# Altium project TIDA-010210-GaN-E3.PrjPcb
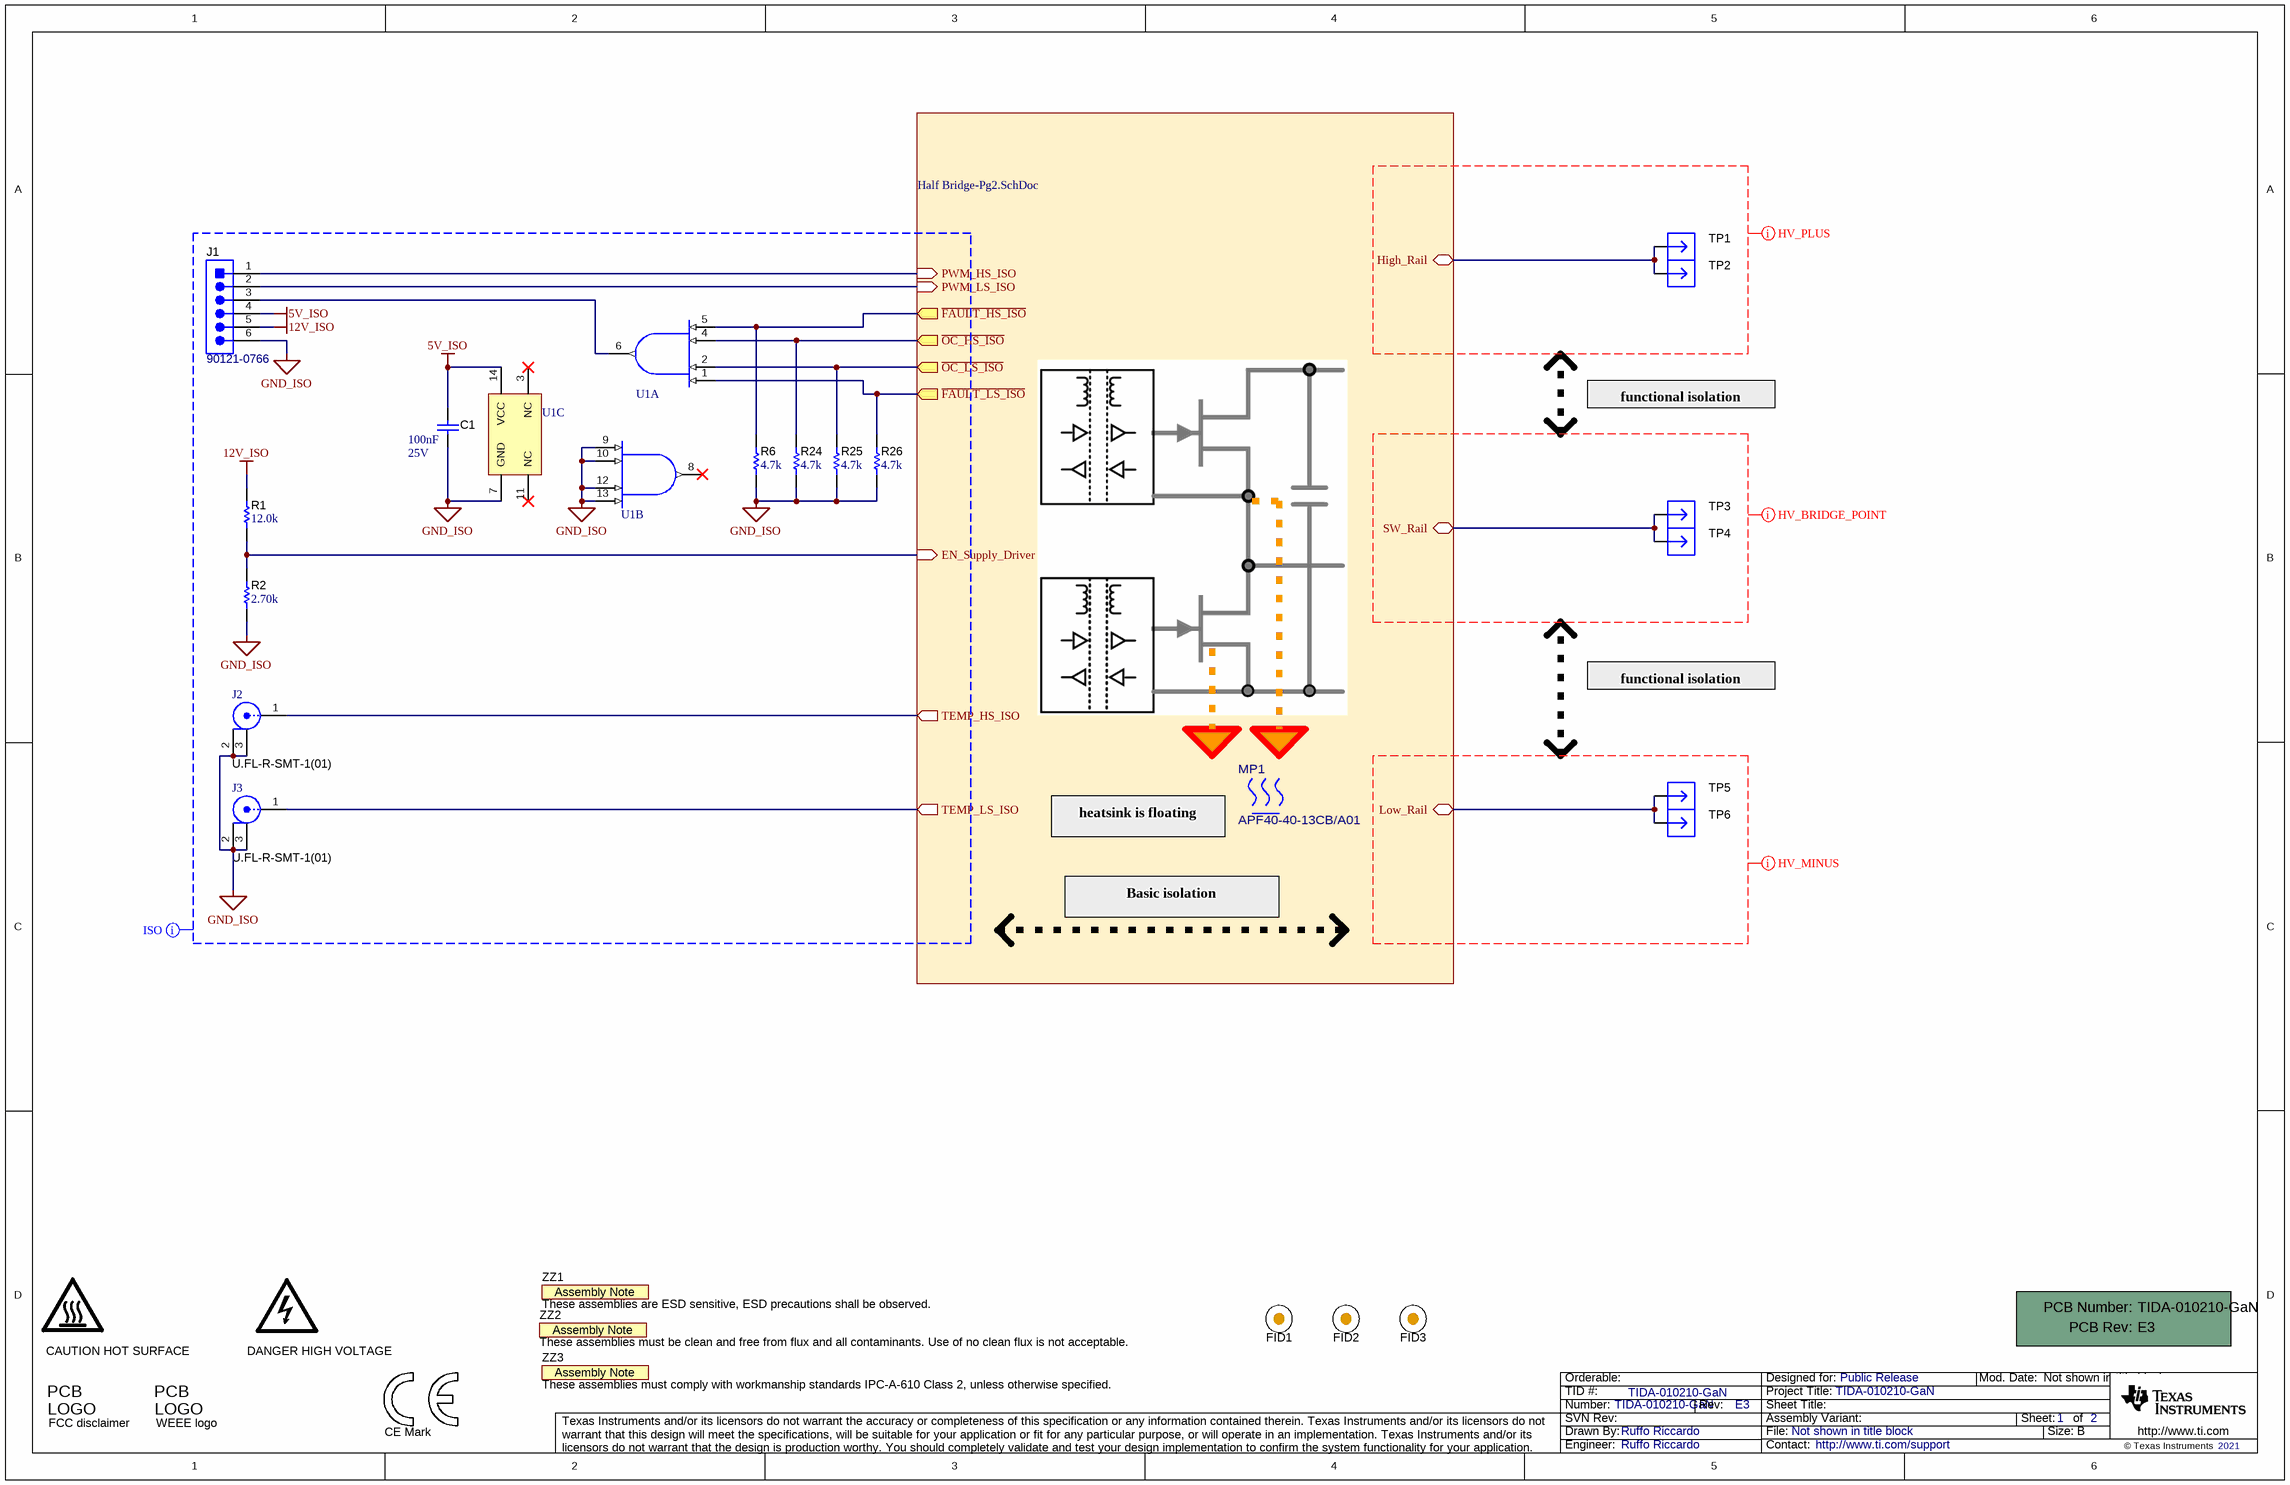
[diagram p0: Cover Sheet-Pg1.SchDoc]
CopyrightYear: 2021; DrawnBy: Ruffo Riccardo; PCB_Layout: Ruffo Riccardo; PCB_Rev: E3; PRJ_Customer: Public Release; PRJ_Engineer: Ruffo Riccardo; PRJ_Number: TIDA-010210-GaN; PRJ_Title: TIDA-010210-GaN; SCH_Rev: E3; TechSupport: http://www.ti.com/support; TID: TIDA-010210-GaN
2 sheets, 108 parts. Net scope: hierarchical (ports join the sheet entries above them; power ports are global).
Board file: TIDA-010210-GaN-E3.PcbDoc
Sheets:
  Cover Sheet-Pg1.SchDoc
    U_Half_Bridge = Half Bridge-Pg2.SchDoc

## Sheet Cover Sheet-Pg1.SchDoc
size 431 x 279 mm; Date: Not shown in title block; ApprovedBy: Not shown in title block; CheckedBy: Not shown in title block; Author: Not shown in title block; CompanyName: Not shown in title block; Engineer: Not shown in title block; Organization: Not shown in title block; Address1: Not shown in title block; Address2: Not shown in title block; Address3: Not shown in title block; Address4: Not shown in title block; DocumentNumber: 1; Revision: Use project parameter SCH_Rev; SheetNumber: 1; SheetTotal: 2; PageSetup: Record=PageOptions¦CenterHorizontal=True¦CenterVertical=True¦PrintScale=1.00¦XCorrection=1.00¦YCorrection=1.00¦PrintKind=0¦BorderSize=5000000¦LeftOffset=0¦BottomOffset=0¦Orientation=2¦PaperLength=1000¦PaperWidth=1000¦Scale=100¦PaperSource=15¦PrintQuality=600¦MediaType=1¦DitherType=10¦PaperKind=Letter¦PrintScaleMode=1

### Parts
!PCB1  Printed Circuit Board  (value not drawn)  (mechanical)
C1  Cap_F: 100nF  VDC_V: 25V  [0603]  (hidden comment: 06033C104JAT2A)
FID1  Fiducial  [Fiducial6.4-20]  (value not drawn)
FID2  Fiducial  [Fiducial6.4-20]  (value not drawn)
FID3  Fiducial  [Fiducial6.4-20]  (value not drawn)
J1  90121-0766  [Molex_90121-0766]
J2  U.FL-R-SMT-1(01)  [CONN_UFL-R-SMT-1]
J3  U.FL-R-SMT-1(01)  [CONN_UFL-R-SMT-1]
LOGO1  CAUTION HOT SURFACE  [IEC_HotSurface_Small]  (no BOM)
LOGO3  DANGER HIGH VOLTAGE  [IEC_HighVoltage_Small]  (no BOM)
Logo5  CE Mark  [CE_Mark_5mm]  (no BOM)
Logo6  FCC disclaimer  [FCC_disclaimer_stacked]  (no BOM)
Logo8  WEEE logo  [WEEE_Minimum]  (no BOM)
MP1  APF40-40-13CB/A01  [FP-APF40-40-13CB-A01_HEATSINK_40MM0_40MM0-MFG]
R1  ValueDisplayed: 12.0k  [0603]  (hidden comment: RC0603FR-0712KL)
R2  ValueDisplayed: 2.70k  [0603]  (hidden comment: RC0603FR-072K7L)
R6  ValueDisplayed: 4.7k  [0603]  (hidden comment: CR0603-JW-472GLF)
R24  ValueDisplayed: 4.7k  [0603]  (hidden comment: CR0603-JW-472GLF)
R25  ValueDisplayed: 4.7k  [0603]  (hidden comment: CR0603-JW-472GLF)
R26  ValueDisplayed: 4.7k  [0603]  (hidden comment: CR0603-JW-472GLF)
TP1  3620-2-32-15-00-00-08-0  [Mill-Max_3620-2-32-xx-00-00-08-0]  (value not drawn)
TP2  3620-2-32-15-00-00-08-0  [Mill-Max_3620-2-32-xx-00-00-08-0]  (value not drawn)
TP3  3620-2-32-15-00-00-08-0  [Mill-Max_3620-2-32-xx-00-00-08-0]  (value not drawn)
TP4  3620-2-32-15-00-00-08-0  [Mill-Max_3620-2-32-xx-00-00-08-0]  (value not drawn)
TP5  3620-2-32-15-00-00-08-0  [Mill-Max_3620-2-32-xx-00-00-08-0]  (value not drawn)
TP6  3620-2-32-15-00-00-08-0  [Mill-Max_3620-2-32-xx-00-00-08-0]  (value not drawn)
U1  SN74AS21D  [D0014A_N]  (value not drawn)  (parts A,B,C of 3)
ZZ1  These assemblies are ESD sensitive, ESD precautions shall be observed.  [AssemblyNote]  (no BOM)
ZZ2  These assemblies must be clean and free from flux and all contaminants. Use of no clean flux is not acceptable.  [AssemblyNote]  (no BOM)
ZZ3  These assemblies must comply with workmanship standards IPC-A-610 Class 2, unless otherwise specified.  [AssemblyNote]  (no BOM)

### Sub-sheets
U_Half_Bridge = Half Bridge-Pg2.SchDoc: TEMP_HS_ISO (out), PWM_HS_ISO (in), TEMP_LS_ISO (out), EN_Supply_Driver (in), PWM_LS_ISO (in), SW_Rail (bidir), High_Rail (bidir), Low_Rail (bidir), ~{OC_LS_ISO} (out), ~{FAULT_LS_ISO} (out), ~{OC_HS_ISO} (out), ~{FAULT_HS_ISO} (out)

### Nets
5V_ISO: C1.1 J1.4 U1.14(VCC)
12V_ISO: J1.5 R1.2
GND_ISO: C1.2 J1.6 J2.2 J2.3 J3.2 J3.3 R2.1 R6.1 R24.1 R25.1 R26.1 U1.7(GND) U1.9(2A) U1.10(2B) U1.12(2C) U1.13(2D)
Low_Rail: TP5.1 TP6.1 ; sheet U_Half_Bridge/Low_Rail
SW_Rail: TP3.1 TP4.1 ; sheet U_Half_Bridge/SW_Rail
EN_Supply_Driver: R1.1 R2.2 ; sheet U_Half_Bridge/EN_Supply_Driver
~{FAULT_HS_ISO}: R6.2 U1.5(1D) ; sheet U_Half_Bridge/~{FAULT_HS_ISO}
~{FAULT_LS_ISO}: R26.2 U1.1(1A) ; sheet U_Half_Bridge/~{FAULT_LS_ISO}
High_Rail: TP1.1 TP2.1 ; sheet U_Half_Bridge/High_Rail
~{OC_HS_ISO}: R24.2 U1.4(1C) ; sheet U_Half_Bridge/~{OC_HS_ISO}
~{OC_LS_ISO}: R25.2 U1.2(1B) ; sheet U_Half_Bridge/~{OC_LS_ISO}
PWM_HS_ISO: J1.1 ; sheet U_Half_Bridge/PWM_HS_ISO
PWM_LS_ISO: J1.2 ; sheet U_Half_Bridge/PWM_LS_ISO
TEMP_HS_ISO: J2.1 ; sheet U_Half_Bridge/TEMP_HS_ISO
TEMP_LS_ISO: J3.1 ; sheet U_Half_Bridge/TEMP_LS_ISO
NetJ1_3: J1.3 U1.6(1Y)

Not connected (* = marked no-connect by the designer): U1 3(NC)* 8(2Y)* 11(NC)*

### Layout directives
net class ISO: 5V_ISO, 12V_ISO, GND_ISO
net class HV_MINUS: (no net found under the mark)
net class HV_BRIDGE_POINT: (no net found under the mark)
net class HV_PLUS: (no net found under the mark)

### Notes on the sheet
- functional isolation
- (near MP1) heatsink is floating
- Basic isolation

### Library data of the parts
!PCB1 = CMP-0003618-2: Manufacturer: Any; PartNumber: TIDA-010210-GaN
C1 = CMP-0006752-5: CAP, CERM, 0.1 uF, 25 V, +/- 5%, X7R, 0603; Manufacturer: AVX; TaMin_C: -55°C; ESR_ohm: 0.05; Polarized: N; SizeAreaWB_mm2: 4.68; Value1: 0.05 ohm; U/M: EA; Value: 0.1uF; TaMax_C: 125°C; SizeZ_mm: 1; SizeX_mm: 1.6; SizeY_mm: 0.8; SizeArea_mm2: 1.28; AEC Category: Q200
FID1-FID3 = CMP-0077181-1: Fiducial mark.  There is nothing to buy or mount.
J1 = CMP-0055334-1: Header, 2.54mm, 6x1, Gold, R/A, TH; Manufacturer: Molex; CNHeader: TRUE; Current_A: 3A; Shrouded: N; Gender: Male; Voltage_V: 350V; Row_Count: 1; Pitch_mm: 2.54; CT: FALSE; Cert_UL: Y
J2 J3 = CMP-0075320-1: Receptacle, Ultra Miniature Coaxial, Male Pin, 50 ohm, SMT; Manufacturer: Hirose Electric Co. Ltd.; CNHeader: False; Gender: Female; ContactFinish: Gold
LOGO1 = CMP-0074837-1: IEC 61010-1 Hot Surface Warning; SymbolCreator: a0412235; Lib Reference: IEC_HotSurface
LOGO3 = CMP-0074835-1: IEC 61010-1 High Voltage Warning; SymbolCreator: a0412235; Lib Reference: IEC_HighVoltage
Logo5 = CMP-0074844-1: SymbolCreator: a0412235
Logo6 = CMP-0074847-1: FCC_disclaimer; Library Reference: Logo
Logo8 = CMP-0074769-1
MP1 = CMP-0093659-2: Heat Sink Assorted (BGA, LGA, CPU, ASIC...) Aluminum - Top Mount; Manufacturer: CTS; Natural Thermal Resistance: 9.9°C/W; Thermal Resistance Forced Air Flow: 2.3°C/W; AEC Qualified: No
R1 = CMP-0022779-5: RES, 12.0 k, 1%, 0.1 W, 0603; Manufacturer: Yageo; Power_W: 100mW; TempCo: 100 ppm/C; Value_Code: 12k0; Value: 12.0k; Res_ohm: 12k; SizeX_mm: 1.6; SizeY_mm: 0.8; SizeZ_mm: 1; Value2: 0.1W; SizeArea_mm2: 1.28; AEC Qualified: N; VDC_V: 75V; AEC Category: Q200; SizeAreaWB_mm2: 4.68
R2 = CMP-0022996-5: RES, 2.70 k, 1%, 0.1 W, 0603; Manufacturer: Yageo; Power_W: 100mW; TempCo: 100 ppm/C; Value_Code: 2k70; Value: 2.70k; Res_ohm: 2.7k; SizeX_mm: 1.6; SizeY_mm: 0.8; SizeZ_mm: 1; Value2: 0.1W; SizeArea_mm2: 1.28; AEC Qualified: N; VDC_V: 75V; AEC Category: Q200; SizeAreaWB_mm2: 4.68
R6 R24-R26 = CMP-0025696-3: RES, 4.7 k, 5%, 0.1 W, 0603; Manufacturer: Bourns; Power_W: 100mW; TempCo: 200 ppm/C; Value_Code: 4k70; U/M: EA; Value: 4.7k; EIA_Code: E24; SizeX_mm: 1.6; SizeY_mm: 0.8; SizeZ_mm: 1; Value2: 0.1W; SizeArea_mm2: 1.28; AEC Qualified: N; VDC_V: 50V; AEC Category: Q200
TP1-TP6 = CMP-0055044-1: PCB Pin, 0.04" DIA, Edge-Mount; Manufacturer: Mill-Max; CompType: PCB Pin; Gender: Male; Row_Count: 1; ContactFinish: Gold; CNHeader: FALSE
U1 = CMP-0054374-1: Dual 4-Input Positive-AND Gates, D0014A, TUBE; Manufacturer: Texas Instruments; F @ Nom Voltage(Max)(Mhz): 125; VCC(Min)(V): 4.5; VCC(Max)(V): 5.5; Voltage(Nom)(V): 5; ICC @ Nom Voltage(Max)(mA): 0.0014; Bits(#): 2; Output Type: TTL; Schmitt Trigger: No; Rating: Catalog; tpd @ Nom Voltage(Max)(ns): 15; Technology Family: AS; Output Drive (IOL/IOH)(Max)(mA): -48/48
ZZ1 = CMP-0077236-1
ZZ2 = CMP-0077237-1
ZZ3 = CMP-0077238-1

## Sheet Half Bridge-Pg2.SchDoc
size 431 x 279 mm; Date: Not shown in title block; ApprovedBy: Not shown in title block; CheckedBy: Not shown in title block; Author: Not shown in title block; CompanyName: Not shown in title block; Engineer: Not shown in title block; Organization: Not shown in title block; Address1: Not shown in title block; Address2: Not shown in title block; Address3: Not shown in title block; Address4: Not shown in title block; DocumentNumber: 2; Revision: Use project parameter SCH_Rev; SheetNumber: 2; SheetTotal: 2; PageSetup: Record=PageOptions¦CenterHorizontal=True¦CenterVertical=True¦PrintScale=1.00¦XCorrection=1.00¦YCorrection=1.00¦PrintKind=0¦BorderSize=5000000¦LeftOffset=0¦BottomOffset=0¦Orientation=2¦PaperLength=1000¦PaperWidth=1000¦Scale=100¦PaperSource=15¦PrintQuality=600¦MediaType=1¦DitherType=10¦PaperKind=Letter¦PrintScaleMode=1
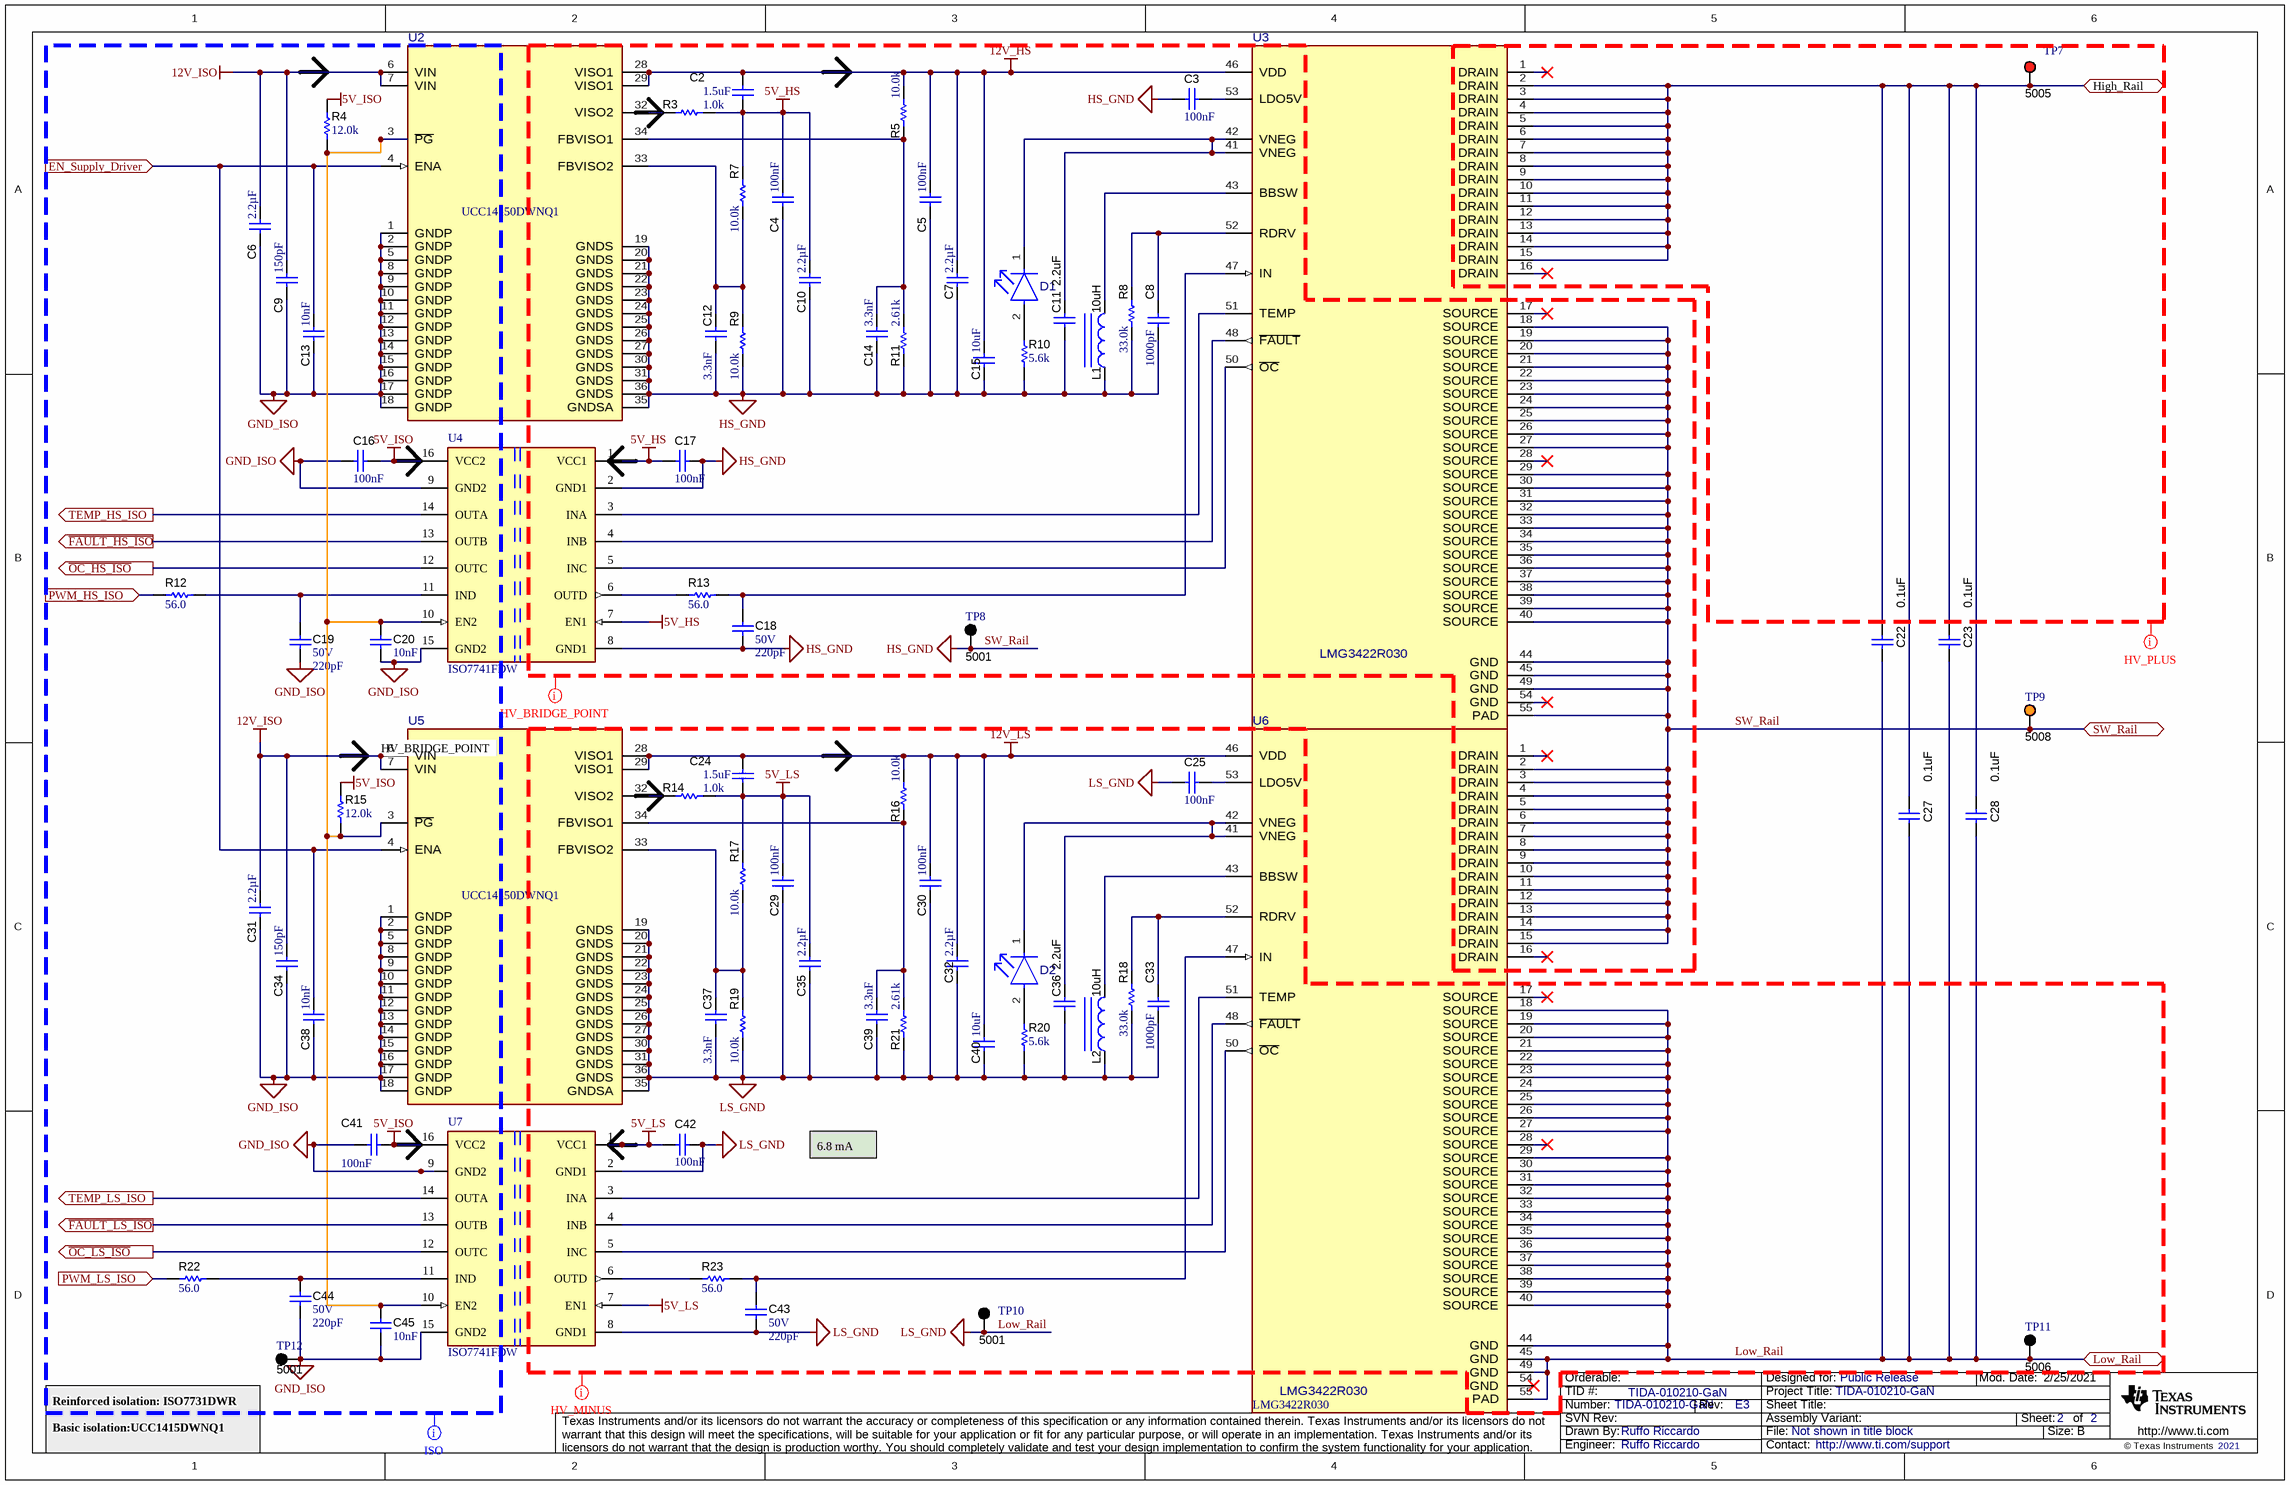
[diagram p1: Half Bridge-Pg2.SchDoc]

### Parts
C2  ValueDisplayed: 1.5uF  [0603]  (hidden comment: C1608X6S1C155K080AC)
C3  Cap_F: 100nF  [0603]  (hidden comment: 06033C104JAT2A)
C4  Cap_F: 100nF  [0603]  (hidden comment: 06033C104JAT2A)
C5  Cap_F: 100nF  [0603]  (hidden comment: 06033C104JAT2A)
C6  ValueDisplayed: 2.2µF  [0603]  (hidden comment: GRM188C71E225KE11D)
C7  ValueDisplayed: 2.2µF  [0603]  (hidden comment: GRM188C71E225KE11D)
C8  ValueDisplayed: 1000pF  [0603]  (hidden comment: C0603C102F3GACTU)
C9  ValueDisplayed: 150pF  [0603]  (hidden comment: GRM1885C1H151JA01D)
C10  ValueDisplayed: 2.2µF  [0603]  (hidden comment: GRM188C71E225KE11D)
C11  ValueDisplayed: 2.2uF  [0805_HV]  (hidden comment: GRM21BR71E225KA73L)
C12  Cap_F: 3.3nF  [0603]  (hidden comment: C0603X332K5RACTU)
C13  Cap_F: 10nF  [0603]  (hidden comment: SR0603X7R103K1NT95(F)#M123A)
C14  Cap_F: 3.3nF  [0603]  (hidden comment: C0603X332K5RACTU)
C15  ValueDisplayed: 10uF  [0805_HV]  (hidden comment: GRM219B31E106MA12)
C16  Cap_F: 100nF  [0603]  (hidden comment: 06033C104JAT2A)
C17  Cap_F: 100nF  [0603]  (hidden comment: 06033C104JAT2A)
C18  VDC_V: 50V  ValueDisplayed: 220pF  [0603]  (hidden comment: C0603C221K5GACTU)
C19  VDC_V: 50V  ValueDisplayed: 220pF  [0603]  (hidden comment: C0603C221K5GACTU)
C20  Cap_F: 10nF  [0603]  (hidden comment: SR0603X7R103K1NT95(F)#M123A)
C22  ValueDisplayed: 0.1uF  [1812_254]  (hidden comment: C1812W104KDRACTU)
C23  ValueDisplayed: 0.1uF  [1812_254]  (hidden comment: C1812W104KDRACTU)
C24  ValueDisplayed: 1.5uF  [0603]  (hidden comment: C1608X6S1C155K080AC)
C25  Cap_F: 100nF  [0603]  (hidden comment: 06033C104JAT2A)
C27  ValueDisplayed: 0.1uF  [1812_254]  (hidden comment: C1812W104KDRACTU)
C28  ValueDisplayed: 0.1uF  [1812_254]  (hidden comment: C1812W104KDRACTU)
C29  Cap_F: 100nF  [0603]  (hidden comment: 06033C104JAT2A)
C30  Cap_F: 100nF  [0603]  (hidden comment: 06033C104JAT2A)
C31  ValueDisplayed: 2.2µF  [0603]  (hidden comment: GRM188C71E225KE11D)
C32  ValueDisplayed: 2.2µF  [0603]  (hidden comment: GRM188C71E225KE11D)
C33  ValueDisplayed: 1000pF  [0603]  (hidden comment: C0603C102F3GACTU)
C34  ValueDisplayed: 150pF  [0603]  (hidden comment: GRM1885C1H151JA01D)
C35  ValueDisplayed: 2.2µF  [0603]  (hidden comment: GRM188C71E225KE11D)
C36  ValueDisplayed: 2.2uF  [0805_HV]  (hidden comment: GRM21BR71E225KA73L)
C37  Cap_F: 3.3nF  [0603]  (hidden comment: C0603X332K5RACTU)
C38  Cap_F: 10nF  [0603]  (hidden comment: SR0603X7R103K1NT95(F)#M123A)
C39  Cap_F: 3.3nF  [0603]  (hidden comment: C0603X332K5RACTU)
C40  ValueDisplayed: 10uF  [0805_HV]  (hidden comment: GRM219B31E106MA12)
C41  Cap_F: 100nF  [0603]  (hidden comment: 06033C104JAT2A)
C42  Cap_F: 100nF  [0603]  (hidden comment: 06033C104JAT2A)
C43  VDC_V: 50V  ValueDisplayed: 220pF  [0603]  (hidden comment: C0603C221K5GACTU)
C44  VDC_V: 50V  ValueDisplayed: 220pF  [0603]  (hidden comment: C0603C221K5GACTU)
C45  Cap_F: 10nF  [0603]  (hidden comment: SR0603X7R103K1NT95(F)#M123A)
D1  KG DELLS1.22-JGKH-24  [FP-KG DELLS1.22-JGKH-24_0603-MFG]  (value not drawn)
D2  KG DELLS1.22-JGKH-24  [FP-KG DELLS1.22-JGKH-24_0603-MFG]  (value not drawn)
L1  ValueDisplayed: 10uH  [WE-LQS_2010]  (hidden comment: 74404020100)
L2  ValueDisplayed: 10uH  [WE-LQS_2010]  (hidden comment: 74404020100)
R3  ValueDisplayed: 1.0k  [0603]  (hidden comment: RC0603JR-071KL)
R4  ValueDisplayed: 12.0k  [0603]  (hidden comment: RC0603FR-0712KL)
R5  ValueDisplayed: 10.0k  [0603]  (hidden comment: M55342K12B10E0T)
R7  ValueDisplayed: 10.0k  [0603]  (hidden comment: M55342K12B10E0T)
R8  ValueDisplayed: 33.0k  [0603]  (hidden comment: RC0603FR-0733KL)
R9  ValueDisplayed: 10.0k  [0603]  (hidden comment: M55342K12B10E0T)
R10  ValueDisplayed: 5.6k  [0603]  (hidden comment: RC0603JR-075K6L)
R11  ValueDisplayed: 2.61k  [0603]  (hidden comment: RC0603FR-072K61L)
R12  ValueDisplayed: 56.0  [0603]  (hidden comment: RC0603FR-0756RL)
R13  ValueDisplayed: 56.0  [0603]  (hidden comment: RC0603FR-0756RL)
R14  ValueDisplayed: 1.0k  [0603]  (hidden comment: RC0603JR-071KL)
R15  ValueDisplayed: 12.0k  [0603]  (hidden comment: RC0603FR-0712KL)
R16  ValueDisplayed: 10.0k  [0603]  (hidden comment: M55342K12B10E0T)
R17  ValueDisplayed: 10.0k  [0603]  (hidden comment: M55342K12B10E0T)
R18  ValueDisplayed: 33.0k  [0603]  (hidden comment: RC0603FR-0733KL)
R19  ValueDisplayed: 10.0k  [0603]  (hidden comment: M55342K12B10E0T)
R20  ValueDisplayed: 5.6k  [0603]  (hidden comment: RC0603JR-075K6L)
R21  ValueDisplayed: 2.61k  [0603]  (hidden comment: RC0603FR-072K61L)
R22  ValueDisplayed: 56.0  [0603]  (hidden comment: RC0603FR-0756RL)
R23  ValueDisplayed: 56.0  [0603]  (hidden comment: RC0603FR-0756RL)
TP7  5005  [Keystone5005]
TP8  5001  [Keystone5001]
TP9  5008  [Keystone5008]
TP10  5001  [Keystone5001]
TP11  5006  [Keystone5006]
TP12  5001  [Keystone5001]
U2  UCC14150DWNQ1  [DWN0036A-MFG]
U3  LMG3422R030  [RQZ0054A-MFG-NV]
U4  ISO7741FDW  [FP-DW0016A-IPC_A]
U5  UCC14150DWNQ1  [DWN0036A-MFG]
U6  LMG3422R030  [RQZ0054A-MFG-NV]
U7  ISO7741FDW  [FP-DW0016A-IPC_A]

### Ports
EN_Supply_Driver (in), High_Rail (bidir), Low_Rail (bidir), PWM_HS_ISO (in), PWM_LS_ISO (in), SW_Rail (bidir), TEMP_HS_ISO (out), TEMP_LS_ISO (out), ~{FAULT_HS_ISO} (out), ~{FAULT_LS_ISO} (out), ~{OC_HS_ISO} (out), ~{OC_LS_ISO} (out)

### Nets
5V_HS: C2.2 C4.1 C10.1 C17.1 R3.2 R7.2 U4.1(VCC1) U4.7(EN1)
5V_ISO: C16.1 C41.1 R4.1 R15.2 U4.16(VCC2) U7.16(VCC2)
5V_LS: C24.2 C29.1 C35.1 C42.1 R14.2 R17.2 U7.1(VCC1) U7.7(EN1)
12V_HS: C2.1 C5.1 C7.1 C15.1 R5.1 U2.28(VISO1) U2.29(VISO1) U3.46(VDD)
12V_ISO: C6.1 C9.1 C31.1 C34.1 U2.6(VIN) U2.7(VIN) U5.6(VIN) U5.7(VIN)
12V_LS: C24.1 C30.1 C32.1 C40.1 R16.1 U5.28(VISO1) U5.29(VISO1) U6.46(VDD)
GND_ISO: C6.2 C9.2 C13.2 C16.2 C19.2 C20.2 C31.2 C34.2 C38.2 C41.2 C44.2 C45.2 TP12.1 U2.1(GNDP) U2.2(GNDP) U2.5(GNDP) U2.8(GNDP) U2.9(GNDP) U2.10(GNDP) U2.11(GNDP) U2.12(GNDP) U2.13(GNDP) U2.14(GNDP) U2.15(GNDP) U2.16(GNDP) U2.17(GNDP) U2.18(GNDP) U4.9(GND2) U4.15(GND2) U5.1(GNDP) U5.2(GNDP) U5.5(GNDP) U5.8(GNDP) U5.9(GNDP) U5.10(GNDP) U5.11(GNDP) U5.12(GNDP) U5.13(GNDP) U5.14(GNDP) U5.15(GNDP) U5.16(GNDP) U5.17(GNDP) U5.18(GNDP) U7.9(GND2) U7.15(GND2)
Low_Rail: C22.2 C23.2 C25.1 C27.2 C28.2 C29.2 C30.2 C32.2 C33.1 C35.2 C36.1 C37.2 C39.2 C40.2 C42.2 C43.2 L2.1 R18.2 R19.1 R20.1 R21.1 TP10.1 TP11.1 U5.19(GNDS) U5.20(GNDS) U5.21(GNDS) U5.22(GNDS) U5.23(GNDS) U5.24(GNDS) U5.25(GNDS) U5.26(GNDS) U5.27(GNDS) U5.30(GNDS) U5.31(GNDS) U5.35(GNDSA) U5.36(GNDS) U6.18(SOURCE) U6.19(SOURCE) U6.20(SOURCE) U6.21(SOURCE) U6.22(SOURCE) U6.23(SOURCE) U6.24(SOURCE) U6.25(SOURCE) U6.26(SOURCE) U6.27(SOURCE) U6.29(SOURCE) U6.30(SOURCE) U6.31(SOURCE) U6.32(SOURCE) U6.33(SOURCE) U6.34(SOURCE) U6.35(SOURCE) U6.36(SOURCE) U6.37(SOURCE) U6.38(SOURCE) U6.39(SOURCE) U6.40(SOURCE) U6.44(GND) U6.45(GND) U6.49(GND) U6.55(PAD) U7.2(GND1) U7.8(GND1) ; port Low_Rail  [also labelled LS_GND]
SW_Rail: C3.1 C4.2 C5.2 C7.2 C8.1 C10.2 C11.1 C12.2 C14.2 C15.2 C17.2 C18.2 L1.1 R8.2 R9.1 R10.1 R11.1 TP8.1 TP9.1 U2.19(GNDS) U2.20(GNDS) U2.21(GNDS) U2.22(GNDS) U2.23(GNDS) U2.24(GNDS) U2.25(GNDS) U2.26(GNDS) U2.27(GNDS) U2.30(GNDS) U2.31(GNDS) U2.35(GNDSA) U2.36(GNDS) U3.18(SOURCE) U3.19(SOURCE) U3.20(SOURCE) U3.21(SOURCE) U3.22(SOURCE) U3.23(SOURCE) U3.24(SOURCE) U3.25(SOURCE) U3.26(SOURCE) U3.27(SOURCE) U3.29(SOURCE) U3.30(SOURCE) U3.31(SOURCE) U3.32(SOURCE) U3.33(SOURCE) U3.34(SOURCE) U3.35(SOURCE) U3.36(SOURCE) U3.37(SOURCE) U3.38(SOURCE) U3.39(SOURCE) U3.40(SOURCE) U3.44(GND) U3.45(GND) U3.49(GND) U3.55(PAD) U4.2(GND1) U4.8(GND1) U6.2(DRAIN) U6.3(DRAIN) U6.4(DRAIN) U6.5(DRAIN) U6.6(DRAIN) U6.7(DRAIN) U6.8(DRAIN) U6.9(DRAIN) U6.10(DRAIN) U6.11(DRAIN) U6.12(DRAIN) U6.13(DRAIN) U6.14(DRAIN) U6.15(DRAIN) ; port SW_Rail  [also labelled HS_GND]
EN_Supply_Driver: C13.1 C38.1 U2.4(ENA) U5.4(ENA) ; port EN_Supply_Driver
~{FAULT_HS_ISO}: U4.13(OUTB) ; port ~{FAULT_HS_ISO}
~{FAULT_LS_ISO}: U7.13(OUTB) ; port ~{FAULT_LS_ISO}
High_Rail: C22.1 C23.1 C27.1 C28.1 TP7.1 U3.2(DRAIN) U3.3(DRAIN) U3.4(DRAIN) U3.5(DRAIN) U3.6(DRAIN) U3.7(DRAIN) U3.8(DRAIN) U3.9(DRAIN) U3.10(DRAIN) U3.11(DRAIN) U3.12(DRAIN) U3.13(DRAIN) U3.14(DRAIN) U3.15(DRAIN) ; port High_Rail
~{OC_HS_ISO}: U4.12(OUTC) ; port ~{OC_HS_ISO}
~{OC_LS_ISO}: U7.12(OUTC) ; port ~{OC_LS_ISO}
PWM_HS_ISO: R12.1 ; port PWM_HS_ISO
PWM_LS_ISO: R22.1 ; port PWM_LS_ISO
TEMP_HS_ISO: U4.14(OUTA) ; port TEMP_HS_ISO
TEMP_LS_ISO: U7.14(OUTA) ; port TEMP_LS_ISO
NetC3_2: C3.2 U3.53(LDO5V)
NetC8_2: C8.2 R8.1 U3.52(RDRV)
NetC11_2: C11.2 D1.1(CATHODE) U3.41(VNEG) U3.42(VNEG)
NetC12_1: C12.1 R7.1 R9.2 U2.33(FBVISO2)
NetC14_1: C14.1 R5.2 R11.2 U2.34(FBVISO1)
NetC18_1: C18.1 R13.2 U3.47(IN)
NetC19_1: C19.1 R12.2 U4.11(IND)
NetC20_1: C20.1 C45.1 R4.2 R15.1 U2.3(~{PG}) U4.10(EN2) U5.3(~{PG}) U7.10(EN2)
NetC25_2: C25.2 U6.53(LDO5V)
NetC33_2: C33.2 R18.1 U6.52(RDRV)
NetC36_2: C36.2 D2.1(CATHODE) U6.41(VNEG) U6.42(VNEG)
NetC37_1: C37.1 R17.1 R19.2 U5.33(FBVISO2)
NetC39_1: C39.1 R16.2 R21.2 U5.34(FBVISO1)
NetC43_1: C43.1 R23.2 U6.47(IN)
NetC44_1: C44.1 R22.2 U7.11(IND)
NetD1_2: D1.2(ANODE) R10.2
NetD2_2: D2.2(ANODE) R20.2
NetL1_2: L1.2 U3.43(BBSW)
NetL2_2: L2.2 U6.43(BBSW)
NetR3_1: R3.1 U2.32(VISO2)
NetR13_1: R13.1 U4.6(OUTD)
NetR14_1: R14.1 U5.32(VISO2)
NetR23_1: R23.1 U7.6(OUTD)
NetU3_48: U3.48(~{FAULT}) U4.4(INB)
NetU3_50: U3.50(~{OC}) U4.5(INC)
NetU3_51: U3.51(TEMP) U4.3(INA)
NetU6_48: U6.48(~{FAULT}) U7.4(INB)
NetU6_50: U6.50(~{OC}) U7.5(INC)
NetU6_51: U6.51(TEMP) U7.3(INA)

Not connected (* = marked no-connect by the designer): U3 1(DRAIN)* 16(DRAIN)* 17(SOURCE)* 28(SOURCE)* 54(GND)*; U6 1(DRAIN)* 16(DRAIN)* 17(SOURCE)* 28(SOURCE)* 54(GND)*

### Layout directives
net class ISO: 5V_ISO, 12V_ISO, GND_ISO
net class HV_MINUS: 5V_LS, 12V_LS, Low_Rail, LS_GND, SW_Rail
net class HV_BRIDGE_POINT: 5V_HS, 5V_LS, 12V_HS, 12V_LS, HS_GND, LS_GND, SW_Rail
net class HV_PLUS: (no net found under the mark)

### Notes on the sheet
- (near R4) Efficiency = 60 % (DC/DC)
  Idd= 56 mA
- 12 V
  0.25 W at 150 kHz = 21 mA
  LED 3 mA
  Current = 24 mA Power@12V= 0.3 W
  5 V
  Digital isolator 6.8 mA
  Current= 6.8 mA Power@5V= 0.035 W
- (near U3) 33 kOhm (100 kV/us)
- (near D1) if LED green is on negative rail supply is ready
- fcutoff=(1/(2*pi*(10k//10k)*3.3nF))= 10 kHz
- 2.5 V will force (10+2.61)/2.61*2.5=12.07 V
- fcutoff=(1/(2*pi*(10k//2.61k)*3.3nF))= 23 kHz
- 5 mA
- 6.8 mA
- 7V between VISO1 and VISO2 C=1.5uF
  5V between VISO2 and GND C=2.2uF
- (near U5) HV_BRIDGE_POINT
- (near R15) Efficiency = 60 % (DC/DC)
  Idd= 56 mA
- (near C28) Nominal DC bus capacitance 644 nF
- (near D2) if LED green is on negative rail supply is ready
- (near U6) 33 kOhm (100 kV/us)
- (near TP12) Reinforced isolation: ISO7731DWR
  Basic isolation:UCC1415DWNQ1

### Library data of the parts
C2 C24 = CMP-0007025-4: CAP, CERM, 1.5 uF, 16 V, +/- 10%, X6S, 0603; Manufacturer: TDK; TaMin_C: -55°C; ESR_ohm: 9.039m; Polarized: N; SizeAreaWB_mm2: 4.68; Value1: 0.009039 ohm; U/M: EA; Value: 1.5uF; TaMax_C: 105°C; SizeZ_mm: 1; SizeX_mm: 1.6; SizeY_mm: 0.8; Value2: 16V; SizeArea_mm2: 1.28; Cap_F: 1.5µF; IRMS_A: 1.73141A; AEC Category: Q200
C3-C5 C16 C17 C25 C29 C30 C41 C42 = CMP-0006752-5: CAP, CERM, 0.1 uF, 25 V, +/- 5%, X7R, 0603; Manufacturer: AVX; TaMin_C: -55°C; ESR_ohm: 0.05; Polarized: N; SizeAreaWB_mm2: 4.68; Value1: 0.05 ohm; U/M: EA; Value: 0.1uF; TaMax_C: 125°C; SizeZ_mm: 1; SizeX_mm: 1.6; SizeY_mm: 0.8; Value2: 25V; SizeArea_mm2: 1.28; AEC Category: Q200
C6 C7 C10 C31 C32 C35 = CMP-0075366-3: CAP, CERM, 2.2 µF, 25 V,+/- 10%, X7S, 0603; Manufacturer: MuRata; TaMin_C: -55°C; Polarized: N; SizeAreaWB_mm2: 4.68; U/M: EA; Value: 2.2uF; TaMax_C: 125°C; SizeZ_mm: 1.0; SizeX_mm: 1.6; SizeY_mm: 0.8; Value2: 25V; SizeArea_mm2: 1.28; AEC Category: Q200
C8 C33 = CMP-0080092-1: CAP, CERM, 1000 pF, 25 V,+/- 1%, C0G/NP0, 0603; Manufacturer: Kemet; Cap_F: 1nF; SizeAreaWB_mm2: 4.68; SizeArea_mm2: 1.28; AEC Qualified: N; AEC Category: Q200; Value: 1000pF; TaMax_C: 125°C; SizeZ_mm: 1; Green_REACh: Passed; TaMin_C: -55°C; VDC_V: 25V; SizeY_mm: 0.8; Green_Lifecycle: Active; U/M: EA; SizeX_mm: 1.6
C9 C34 = CMP-0007185-4: CAP, CERM, 150 pF, 50 V, +/- 5%, C0G/NP0, 0603; Manufacturer: MuRata; TaMin_C: -55°C; Polarized: N; SizeAreaWB_mm2: 4.68; Value1: Unknown; U/M: EA; Value: 150pF; TaMax_C: 125°C; SizeZ_mm: 1; SizeX_mm: 1.6; SizeY_mm: 0.8; Value2: 50V; SizeArea_mm2: 1.28; AEC Category: Q200
C11 C36 = CMP-0008342-2: CAP, CERM, 2.2 uF, 25 V, +/- 10%, X7R, 0805; Manufacturer: MuRata; Alternate PartNumber: GRM219R61E225KA12D; Polarized: N; Value: 2.2uF; U/M: EA; Cap_F: 2.2µF; ESR_ohm: 5m; Value1: 0.005 ohm; VDC_V: 25V; TaMin_C: -55°C; TaMax_C: 125°C; Cap_Case: 0805; SizeArea_mm2: 2.5; SizeAreaWB_mm2: 6.75; SizeX_mm: 2; SizeY_mm: 1.25; SizeZ_mm: 1.45; AEC Category: Q200
C12 C14 C37 C39 = CMP-0006985-4: CAP, CERM, 3300 pF, 50 V, +/- 10%, X7R, 0603; Manufacturer: Kemet; TaMin_C: -55°C; Polarized: N; SizeAreaWB_mm2: 4.68; Value1: Unknown; U/M: EA; Value: 3300pF; TaMax_C: 125°C; SizeZ_mm: 1; SizeX_mm: 1.6; SizeY_mm: 0.8; Value2: 50V; SizeArea_mm2: 1.28; AEC Category: Q200
C13 C20 C38 C45 = CMP-0079721-1: CAP, CERM, 0.01 µF, 25 V,+/- 10%, X7R, 0603; Manufacturer: Presidio Components; TaMin_C: -55°C; Polarized: N; SizeAreaWB_mm2: 4.68; U/M: EA; Value: 0.01uF; TaMax_C: 125°C; SizeZ_mm: 1; SizeX_mm: 1.6; SizeY_mm: 0.8; Value2: 25V; SizeArea_mm2: 1.28; AEC Category: Q200; ValueDisplayed: 0.01µF
C15 C40 = CMP-0008183-2: CAP, CERM, 10 uF, 25 V, +/- 20%, B, 0805; Manufacturer: MuRata; TaMin_C: -25°C; Polarized: N; SizeAreaWB_mm2: 6.75; Value1: Unknown; U/M: EA; Value: 10uF; TaMax_C: 85°C; SizeZ_mm: 1.45; SizeX_mm: 2; SizeY_mm: 1.25; Cap_Case: 0805; Value2: 25V; SizeArea_mm2: 2.5; Cap_F: 10µF; AEC Category: Q200
C18 C19 C43 C44 = CMP-0006894-4: CAP, CERM, 220 pF, 50 V, +/- 10%, C0G/NP0, 0603; Manufacturer: Kemet; TaMin_C: -55°C; Polarized: N; SizeAreaWB_mm2: 4.68; Value1: Unknown; U/M: EA; Value: 220pF; TaMax_C: 125°C; SizeZ_mm: 1; SizeX_mm: 1.6; SizeY_mm: 0.8; SizeArea_mm2: 1.28; AEC Category: Q200
C22 C23 C27 C28 = CMP-0009326-2: CAP, CERM, 0.1 uF, 1000 V, +/- 10%, X7R, 1812; Manufacturer: Kemet; Polarized: N; Value: 0.1uF; U/M: EA; Cap_F: 100nF; Value1: Unknown; VDC_V: 1kV; Value2: 1000V; TaMin_C: -55°C; TaMax_C: 125°C; Cap_Case: 1812; AEC Category: Q200; SizeArea_mm2: 14.4; SizeAreaWB_mm2: 23.1; SizeX_mm: 4.5; SizeY_mm: 3.2; SizeZ_mm: 2.54
D1 D2 = CMP-0093310-1: Standard LEDs - SMD Green TOPLED E 1608; Manufacturer: Osram Opto; AEC Grade: Grade 2; LambdaP: 572nm; SizeZ_mm: 0.7mm; LuminousFlux_PhiV: 0.016-0.0295lm; Luminous Intensity: 4.5-9.7mcd; LambdaD: 570nm; Tjmax_C: 125°C; Angle: 120°; Led Orientation: Top View; Forward Current: 2mA; Vf_V: 1.8V; AEC Qualified: Yes; Vr_V: 12V
L1 L2 = CMP-0063789-1: Inductor, 10 uH, 0.5 A, 0.85 ohm, SMD; Manufacturer: Wurth Elektronik; Value: 10uH; Ind_H: 10µH; Imax_A: 5dA; Irms: 0.5A @ 40C rise; Isat: 0.6A @ 30% inductance drop; DCR_ohm: 8.5d; Value2: 0.5A; SizeAreaWB_mm2: 7.8; SizeArea_mm2: 3.2; SizeX_mm: 2; SizeY_mm: 1.6; SizeZ_mm: 1; AEC Category: Q200; AEC Qualified: N
R3 R14 = CMP-0025899-5: RES, 1.0 k, 5%, 0.1 W, 0603; Manufacturer: Yageo; Power_W: 100mW; TempCo: 100 ppm/C; Value_Code: 1k00; Value: 1.0k; EIA_Code: E24; Res_ohm: 1k; SizeX_mm: 1.6; SizeY_mm: 0.8; SizeZ_mm: 1; Value2: 0.1W; SizeArea_mm2: 1.28; AEC Qualified: N; VDC_V: 75V; AEC Category: Q200; SizeAreaWB_mm2: 4.68
R4 R15 = CMP-0022779-5: as R1 on sheet Cover Sheet-Pg1
R5 R7 R9 R16 R17 R19 = CMP-0080488-1: RES, 10.0 k, 1%, 0.1 W, 0603; Manufacturer: TT Electronics/IRC; Power_W: 100mW; TempCo: 100 ppm/C; SizeAreaWB_mm2: 4.68; Value_Code: 10k0; Value: 10.0k; EIA_Code: E96; Res_ohm: 10k; SizeX_mm: 1.6; SizeY_mm: 0.8; SizeZ_mm: 1; Value2: 0.1W; SizeArea_mm2: 1.28; AEC Qualified: N; AEC Category: Q200
R8 R18 = CMP-0023037-5: RES, 33.0 k, 1%, 0.1 W, 0603; Manufacturer: Yageo; Power_W: 100mW; TempCo: 100 ppm/C; Value_Code: 33k0; Value: 33.0k; Res_ohm: 33k; SizeX_mm: 1.6; SizeY_mm: 0.8; SizeZ_mm: 1; Value2: 0.1W; SizeArea_mm2: 1.28; AEC Qualified: N; VDC_V: 75V; AEC Category: Q200; SizeAreaWB_mm2: 4.68
R10 R20 = CMP-0025933-5: RES, 5.6 k, 5%, 0.1 W, 0603; Manufacturer: Yageo; Power_W: 100mW; TempCo: 100 ppm/C; Value_Code: 5k60; Value: 5.6k; EIA_Code: E24; SizeX_mm: 1.6; SizeY_mm: 0.8; SizeZ_mm: 1; Value2: 0.1W; SizeArea_mm2: 1.28; AEC Qualified: N; VDC_V: 75V; AEC Category: Q200; SizeAreaWB_mm2: 4.68
R11 R21 = CMP-0022993-5: RES, 2.61 k, 1%, 0.1 W, 0603; Manufacturer: Yageo; Power_W: 100mW; TempCo: 100 ppm/C; Value_Code: 2k61; Value: 2.61k; EIA_Code: E96; SizeX_mm: 1.6; SizeY_mm: 0.8; SizeZ_mm: 1; Value2: 0.1W; SizeArea_mm2: 1.28; AEC Qualified: N; VDC_V: 75V; AEC Category: Q200; SizeAreaWB_mm2: 4.68
R12 R13 R22 R23 = CMP-0023188-5: RES, 56.0, 1%, 0.1 W, 0603; Manufacturer: Yageo; Power_W: 100mW; TempCo: 100 ppm/C; Value_Code: 56R0; Value: 56.0; Res_ohm: 56; SizeX_mm: 1.6; SizeY_mm: 0.8; SizeZ_mm: 1; Value2: 0.1W; SizeArea_mm2: 1.28; AEC Qualified: N; VDC_V: 75V; AEC Category: Q200; SizeAreaWB_mm2: 4.68
TP7 = CMP-0055142-1: Test Point, Compact, Red, TH; Manufacturer: Keystone; CNHeader: FALSE; Green_Lifecycle: Active; Green_REACh: Passed; ContactFinish: Silver; CT: TRUE
TP8 TP10 TP12 = CMP-0055138-1: Test Point, Miniature, Black, TH; Manufacturer: Keystone; CNHeader: FALSE; Green_Lifecycle: Active; Green_REACh: Passed; ContactFinish: Silver; CT: TRUE
TP9 = CMP-0055145-1: Test Point, Compact, Orange, TH; Manufacturer: Keystone; CNHeader: FALSE; Green_Lifecycle: Active; Green_REACh: Passed; ContactFinish: Silver; CT: TRUE
TP11 = CMP-0055143-1: Test Point, Compact, Black, TH; Manufacturer: Keystone; CNHeader: FALSE; Green_Lifecycle: Active; Green_REACh: Passed; ContactFinish: Silver; CT: TRUE
U2 U5 = CMP-0093317-1: 1W, 15V-Vin, 15V-Vout, High-Efficiency, >3 kVRMS Isolated DC-DC Converter; Manufacturer: Texas Instruments; Max Supply Voltage: 27V; TJmax_C: +150°C; TaMin_C: -40°C; Standoff Height: 0.1mm; SizeZ_mm: 3.55mm; AEC Grade: Grade 1; Max Power Dissipation: 540mW; Number Of Outputs: 2; AEC Qualified: Yes; Output Voltage: 2.5-17V; Min Supply Voltage: 10V; Output Type: AdjustableProgrammable; Switching Topology: Buck; TaMax_C: +125°C
U3 U6 = CMP-0088545-3: 600-V 30-mΩ Integrated GaN Power Stage with Smart Driver; Part Number: LMG3425R030RQZT; Manufacturer: Texas Instruments; AEC Category: Q200; SizeZ_mm: 0.9mm; Number Of Outputs: 1; Max Supply Voltage: 18V; Output Voltage: 480V; Min Supply Voltage: 7.5V; TJmax_C: +125°C; Nominal Supply Current: 13mA; AEC Qualified: No; CompType: IC; Standoff Height: 0mm
U4 U7 = CMP-04872-000092-1: DGTL ISO 5000VRMS 4CH GP 16SOIC; Manufacturer: Texas Instruments; Number of Channels: 4; Max Supply Voltage: 5.5V; Min Supply Voltage: 2.25V; Propagation Delay: 10.7ns

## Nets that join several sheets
5V_ISO: Cover Sheet-Pg1 (C1.1 J1.4 U1.14), Half Bridge-Pg2 (6 pins)
12V_ISO: Cover Sheet-Pg1 (J1.5 R1.2), Half Bridge-Pg2 (8 pins)
GND_ISO: Cover Sheet-Pg1 (16 pins), Half Bridge-Pg2 (45 pins)
Low_Rail: Cover Sheet-Pg1 (TP5.1 TP6.1), Half Bridge-Pg2 (64 pins)
SW_Rail: Cover Sheet-Pg1 (TP3.1 TP4.1), Half Bridge-Pg2 (74 pins)
EN_Supply_Driver: Cover Sheet-Pg1 (R1.1 R2.2), Half Bridge-Pg2 (C13.1 C38.1 U2.4 U5.4)
~{FAULT_HS_ISO}: Cover Sheet-Pg1 (R6.2 U1.5), Half Bridge-Pg2 (U4.13)
~{FAULT_LS_ISO}: Cover Sheet-Pg1 (R26.2 U1.1), Half Bridge-Pg2 (U7.13)
High_Rail: Cover Sheet-Pg1 (TP1.1 TP2.1), Half Bridge-Pg2 (19 pins)
~{OC_HS_ISO}: Cover Sheet-Pg1 (R24.2 U1.4), Half Bridge-Pg2 (U4.12)
~{OC_LS_ISO}: Cover Sheet-Pg1 (R25.2 U1.2), Half Bridge-Pg2 (U7.12)
PWM_HS_ISO: Cover Sheet-Pg1 (J1.1), Half Bridge-Pg2 (R12.1)
PWM_LS_ISO: Cover Sheet-Pg1 (J1.2), Half Bridge-Pg2 (R22.1)
TEMP_HS_ISO: Cover Sheet-Pg1 (J2.1), Half Bridge-Pg2 (U4.14)
TEMP_LS_ISO: Cover Sheet-Pg1 (J3.1), Half Bridge-Pg2 (U7.14)

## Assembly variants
001: not fitted C3 C12 C14 C25 C37 C39 H1 R2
